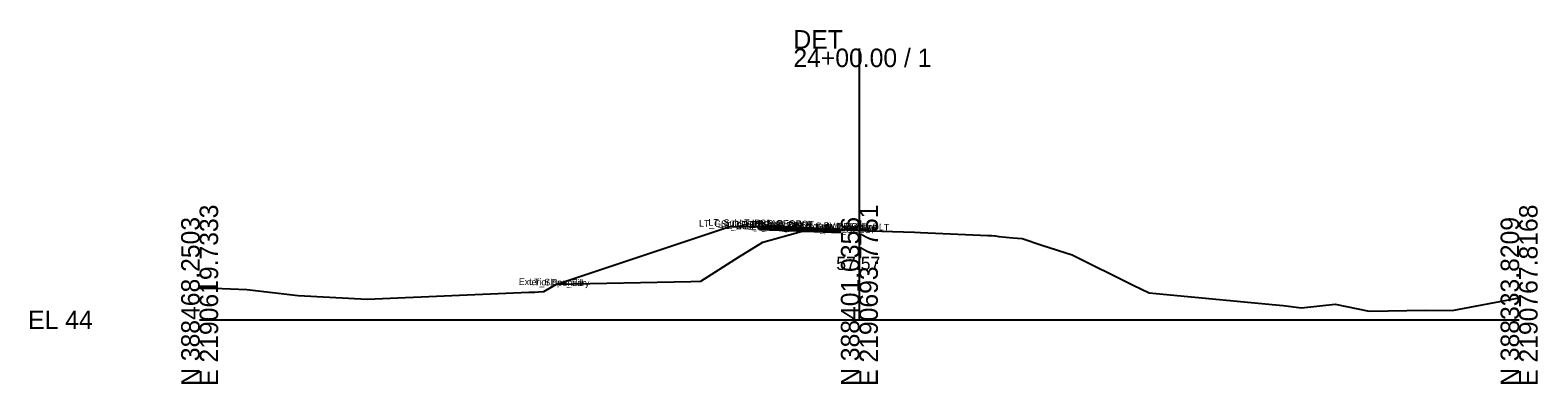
# Model space of a CAD drawing. Extents: x -26 to 1203, y -10 to 9543.
# Drawn here: x 974.3 to 1202.8, y 3990.3 to 4043.9 of the extents above; entities that cross this region are included whole.
import ezdxf

# ---------------------------------------------------------------- set-up
doc = ezdxf.new("R2010")
doc.units = 0
for name, color, linetype in [('Default', 7, 'Continuous'), ('Exist Cross Section Cell', 7, 'Continuous'), ('Exist XS Center Line Elevation Label', 7, 'Continuous'), ('Exist XS Ground Line', 7, 'Continuous'), ('Prop CMT Pvmt Course 1', 7, 'Continuous'), ('Prop CMT Pvmt Course 2', 7, 'Continuous'), ('Prop CMT Pvmt Surface', 7, 'Continuous'), ('Prop CMT Pvmt Surface Shoulder', 7, 'Continuous'), ('Prop CMT Shld Paved Course 1', 7, 'Continuous'), ('Prop CMT Shld Paved Course 2', 7, 'Continuous'), ('Prop CMT Slope Grass', 7, 'Continuous'), ('Prop CMT Subgrade Earthwork', 7, 'Continuous'), ('Scratch_Level_0', 7, 'Continuous')]:
    doc.layers.add(name, color=color, linetype=linetype)

msp = doc.modelspace()

# ---------------------------------------------------------------- linework, layer by layer
at = {"layer": 'Exist Cross Section Cell'}
for p, q in [((1100, 4000), (1100, 4041.13)), ((1000, 4000), (1100, 4000)), ((1100, 4000), (1200, 4000))]:
    msp.add_line(p, q, dxfattribs=at)
at = {"layer": 'Exist XS Ground Line'}
for p, q in [((1085.35, 4011.81), (1091.19, 4013.42)), ((1091.19, 4013.42), (1095.28, 4013.67)), ((1095.28, 4013.67), (1095.57, 4013.71)), ((1095.57, 4013.71), (1096.65, 4013.71)), ((1096.65, 4013.71), (1097.09, 4013.69)), ((1097.09, 4013.69), (1100.05, 4013.57)), ((1100.05, 4013.57), (1108.36, 4013.29)), ((1108.36, 4013.29), (1109.27, 4013.26)), ((1109.27, 4013.26), (1119.46, 4012.8)), ((1081.68, 4009.49), (1085.35, 4011.81)), ((1119.46, 4012.8), (1120.02, 4012.79)), ((1120.02, 4012.79), (1120.56, 4012.75)), ((1120.56, 4012.75), (1121.14, 4012.66)), ((1121.14, 4012.66), (1123.25, 4012.46)), ((1123.25, 4012.46), (1124.66, 4012.32)), ((1124.66, 4012.32), (1127.66, 4011.31)), ((1127.66, 4011.31), (1132.27, 4009.87)), ((1075.97, 4005.88), (1081.68, 4009.49)), ((1132.27, 4009.87), (1141.49, 4005.26)), ((1000, 4004.83), (1002.22, 4004.83)), ((1002.22, 4004.83), (1007.16, 4004.62)), ((1007.16, 4004.62), (1014.92, 4003.71)), ((1025.39, 4003.14), (1049.91, 4004.21)), ((1049.91, 4004.21), (1050.79, 4004.21)), ((1050.79, 4004.21), (1051.35, 4004.25)), ((1051.35, 4004.25), (1052.18, 4004.32)), ((1052.18, 4004.32), (1054.09, 4005.42)), ((1054.09, 4005.42), (1074.44, 4005.81)), ((1074.44, 4005.81), (1075.97, 4005.88)), ((1141.49, 4005.26), (1143.94, 4004.11)), ((1143.94, 4004.11), (1147.13, 4003.79)), ((1014.92, 4003.71), (1025.39, 4003.14)), ((1147.13, 4003.79), (1163.12, 4002.3)), ((1163.12, 4002.3), (1164.25, 4002.18)), ((1164.25, 4002.18), (1166.99, 4001.85)), ((1166.99, 4001.85), (1172.1, 4002.37)), ((1172.1, 4002.37), (1177.27, 4001.34)), ((1189.86, 4001.43), (1200, 4003.35)), ((1177.27, 4001.34), (1185.84, 4001.49)), ((1185.84, 4001.49), (1189.86, 4001.43))]:
    msp.add_line(p, q, dxfattribs=at)
at = {"layer": 'Prop CMT Pvmt Course 1'}
for points in [[(1097.1, 4013.74), (1087.86, 4014.11)], [(1087.86, 4014.11), (1087.86, 4013.86)], [(1087.86, 4013.86), (1097.1, 4013.49)], [(1097.1, 4013.49), (1097.1, 4013.74)]]:
    msp.add_lwpolyline(points, dxfattribs=at)
at = {"layer": 'Prop CMT Pvmt Course 2'}
for points in [[(1097.1, 4013.49), (1087.86, 4013.86)], [(1087.86, 4013.86), (1087.86, 4013.61)], [(1087.86, 4013.61), (1097.1, 4013.24)], [(1097.1, 4013.24), (1097.1, 4013.49)]]:
    msp.add_lwpolyline(points, dxfattribs=at)
at = {"layer": 'Prop CMT Pvmt Surface'}
msp.add_lwpolyline([(1097.1, 4013.74), (1087.86, 4014.11)], dxfattribs=at)
at = {"layer": 'Prop CMT Pvmt Surface Shoulder'}
msp.add_lwpolyline([(1087.86, 4014.11), (1085.86, 4014.19)], dxfattribs=at)
at = {"layer": 'Prop CMT Shld Paved Course 1'}
for points in [[(1087.86, 4014.11), (1085.86, 4014.19), (1085.62, 4013.95)], [(1085.62, 4013.95), (1087.86, 4013.86)], [(1087.86, 4013.86), (1087.86, 4014.11)]]:
    msp.add_lwpolyline(points, dxfattribs=at)
at = {"layer": 'Prop CMT Shld Paved Course 2'}
for points in [[(1087.86, 4013.86), (1085.62, 4013.95), (1085.12, 4013.97), (1084.88, 4013.73)], [(1084.88, 4013.73), (1087.86, 4013.61)], [(1087.86, 4013.61), (1087.86, 4013.86)]]:
    msp.add_lwpolyline(points, dxfattribs=at)
at = {"layer": 'Prop CMT Slope Grass'}
for points in [[(1080.22, 4014.08), (1053.71, 4005.2)], [(1085.86, 4014.19), (1080.22, 4014.08)]]:
    msp.add_lwpolyline(points, dxfattribs=at)
at = {"layer": 'Prop CMT Subgrade Earthwork'}
for points in [[(1084.88, 4013.73), (1084.45, 4014.16)], [(1087.86, 4013.61), (1084.88, 4013.73)], [(1087.86, 4013.61), (1097.1, 4013.24), (1097.11, 4013.69)]]:
    msp.add_lwpolyline(points, dxfattribs=at)

# ---------------------------------------------------------------- texts
at = {"layer": 'Default'}
msp.add_text('-', height=0.0001, dxfattribs=at).set_placement((1000, 4000))
at = {"layer": 'Exist Cross Section Cell'}
for s, p in [('DET', (1090, 4041.13)), ('24+00.00 / 1', (1090, 4038.33)), ('EL 44', (974, 3998.6))]:
    msp.add_text(s, height=2.8, dxfattribs=at).set_placement(p)
for s, p in [('N 388468.2503', (1000, 3990)), ('E 2190619.7333', (1002.8, 3990)), ('N 388401.0356', (1100, 3990)), ('E 2190693.7751', (1102.8, 3990)), ('N 388333.8209', (1200, 3990)), ('E 2190767.8168', (1202.8, 3990))]:
    msp.add_text(s, height=2.8, rotation=90, dxfattribs=at).set_placement(p)
at = {"layer": 'Exist XS Center Line Elevation Label'}
msp.add_text('57.57', height=2, dxfattribs=at).set_placement((1096.49, 4007.57))
at = {"layer": 'Scratch_Level_0'}
for s, p in [('LT_GS_OS_CTL', (1075.68, 4014.16)), ('LT_Sub_Trench_Out_DLT', (1077.1, 4014.3)), ('LT_Sub_Trench_Out', (1078.99, 4013.84)), ('LT_PS2_Shelf_Out', (1079.78, 4014.07)), ('LT_PS2_OEOP', (1081.41, 4014.03)), ('LT_PS1_OEOP', (1081.77, 4014.27)), ('LT_PV2_OEOT', (1083.6, 4013.94)), ('LT_Sub_OEOT', (1083.63, 4013.69)), ('LT_PV1_OEOT', (1083.72, 4014.19)), ('LT_Sub_OEEOP_DLT', (1091.06, 4013.81)), ('Exterior Boundary', (1091.77, 4013.8)), ('LT_PV2_OEEOP', (1092.49, 4013.58)), ('LT_Sub_OEEOP', (1092.51, 4013.33)), ('PV1_PGL', (1094.57, 4013.79)), ('Exterior Boundary', (1048.37, 4005.31)), ('LT_Slope_Fill', (1049.94, 4005.28))]:
    msp.add_text(s, height=1, rotation=358.8836, dxfattribs=at).set_placement(p)

doc.saveas('drawing.dxf')
